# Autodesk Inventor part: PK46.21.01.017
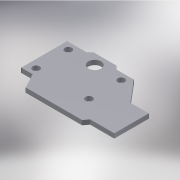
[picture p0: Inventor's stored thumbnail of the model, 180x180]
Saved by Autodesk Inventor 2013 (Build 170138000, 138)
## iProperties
Created: 2005-04
Part Number: PK46.21.01.017
Material: Steel, Mild
Document SubType Name: Modeling
Designer: salex
Manufacturer: Standard
Standards Organization: Custom
Density: 7.86 g/cm^3
Author: salex
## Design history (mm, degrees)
sketch "Эскиз1"
  geometry: L1 (0, 0)-(85, 0); L2 (85, 0)-(100, 15); L3 (100, 15)-(200, 15); L4 (200, 15)-(215, 0); L5 (215, 0)-(290, 0); L6 (290, 0)-(370, -95); L7 (370, -95)-(450, -95); L8 (450, -95)-(450, -245); L9 (450, -245)-(345, -245); L10 (345, -245)-(330, -265); L11 (330, -265)-(85, -265); L12 (85, -265)-(50, -200); L13 (50, -200)-(0, -200); L14 (0, -200)-(0, 0); C1 r 15 at (35, -30); C2 r 15 at (35, -170); C3 r 15 at (265, -30); C4 r 15 at (265, -170); C5 r 27.5 at (150, -30)
  constraints: 28 end point, 6 parallel, 5 centre point, 3 equal radius, 2 collinear, 1 horizontal, 1 perpendicular, 1 other
  dimensions: "d0" = 30 diameter of C1; "d2" = 140 distance of C2.centre C1.centre; "d3" = 0 horizontal distance of C2.centre C1.centre; "d4" = 0 vertical distance of C4.centre C2.centre; "d5" = 0 vertical distance of C3.centre C1.centre; "d6" = 0 horizontal distance of C4.centre C3.centre; "d7" = 230 distance of C3.centre C1.centre; "d8" = 115 distance of C5.centre C1.centre (= 0.5 x d7); "d9" = 0 vertical distance of C1.centre C5.centre; "d10" = 55 diameter of C5; "d11" = 35 distance from line of C1.centre L14; "d12" = 30 distance from line of C2.centre L13; "d13" = 200 distance between parallel lines of L1 L13; "d14" = 65 distance between parallel lines of L11 L13; "d15" = 280 distance between parallel lines of L11 L3; "d16" = 15 horizontal distance of L1.end L2.end; "d17" = 100 distance from line of L2.end L14; "d18" = 100 distance of L2.end L3.end; "d19" = 15 horizontal distance of L3.end L4.end; "d20" = 35 horizontal distance of L11.end L12.end; "d21" = 85 distance from line of L11.end L14; "d22" = 80 distance of L6.end L7.end; "d23" = 150 distance of L7.end L8.end; "d24" = 20 vertical distance of L9.end L10.end; "d25" = 15 horizontal distance of L9.end L10.end; "d26" = 160 distance from line of L8 L5.end; "d27" = 450 distance between parallel lines of L8 L14; "d28" = 245 distance of L10.end L11.end
extrude "Выдавливание1" new body sketch "Эскиз1" distance "d29" = 20; taper "d30" = 0 deg
body "Solid1"
